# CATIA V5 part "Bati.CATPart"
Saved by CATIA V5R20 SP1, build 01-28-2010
Part number: Bati
Bounding box of the stored display mesh (mm): x -64.269 to 244.867, y -28.958 to 420.512, z -389.838 to 29.967
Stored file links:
  C:\Users\RENARD Simon\Documents\Cours IFMA\2ème année\IAO\Bati.CATPart
  C:\Users\RENARD Simon\Documents\Cours IFMA\2ème année\IAO\Trainattero.CATProduct
  C:\Users\RENARD Simon\Documents\Cours IFMA\2ème année\IAO\Sqbati.CATPart
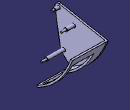
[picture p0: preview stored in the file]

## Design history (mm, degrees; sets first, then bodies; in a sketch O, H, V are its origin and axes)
Set1
  Plane1: linked copy from another document
  Line1 to Line3: linked copy from another document
Body1 (main body)
  Sketch1 on Plane1, origin (-63.6551, 1.3036, 0), H (0.0205, 0.9998, 0), V (0, 0, 1)
    point P1 (116.5347, -389.838)
    line L1 (116.5347, -389.838) -> (26.4996, -310.5054)
    arc A1 centre (46.3327, -287.9966) radius 30 from (26.4996, -310.5054) to (16.7136, -292.7617) cw
    point P3 (46.3327, -287.9966)
    line L2 (16.7136, -292.7617) -> (-29.6191, -4.7651)
    arc A2 centre (0, 0) radius 30 from (-29.6191, -4.7651) to (4.8723, 29.6017) cw
    point P6 (0, 0)
    line L3 (4.8723, 29.6017) -> (419.2961, -38.6108)
    point P8 (419.2961, -38.6108)
    reference projected point E1 (46.3327, -287.9966) from Line2
    reference projected point E2 (0, 0) from Line1
    spline S1 through (116.5347, -389.838) (177.4045, -353.8746) (419.2961, -38.6108)
    point P9 (116.5347, -389.838)
    point P10 (419.2961, -38.6108)
    radius A1 = 30
    radius A2 = 30
    length L1 = 120
    length L3 = 420
    tangency: A1 L1, A2 L2, L2 A1, L3 A2
    coincidence: P3 E1, P6 E2, P9 L1, P10 P8, P9 P1
  Pad1: profile Sketch1, direction (0.9998, -0.0205, 0), length 15
  Sketch2 on end face of Pad1, origin (-48.6582, 0.9965, 0), H (0.0205, 0.9998, 0), V (0, 0, 1)
    spline S1 through (116.5347, -389.838) (193.2598, -342.5189) (419.2961, -38.6108)
    reference projected point E1 (116.5347, -389.838) from vertex [face of Pad1 from Sketch1.L1 | end face of Pad1 | face of Pad1 from Sketch1.S1]
    reference projected point E2 (419.2961, -38.6108) from vertex [face of Pad1 from Sketch1.L3 | end face of Pad1 | face of Pad1 from Sketch1.S1]
    spline S2 through (105.2803, -379.9214) (214.7918, -307.121) (404.4952, -36.1746)
    reference projected line E3 (28.2255, -312.0261) -> (80.4295, -358.0246) from edge [face of Pad1 from Sketch1.L1 | end face of Pad1]
    reference projected line E4 (306.2958, -20.0114) -> (4.8723, 29.6017) from edge [face of Pad1 from Sketch1.L3 | end face of Pad1]
    line L1 (419.2961, -38.6108) -> (404.4952, -36.1746)
    point P1 (404.4952, -36.1746)
    point P2 (419.2961, -38.6108)
    line L2 (116.5347, -389.838) -> (105.2803, -379.9214)
    point P3 (105.2803, -379.9214)
    point P4 (116.5347, -389.838)
    reference projected curve E5 from edge [face of Pad1 from Sketch1.S1 | end face of Pad1]
    reference projected line E6 (306.2958, -20.0114) -> (4.8723, 29.6017) from edge [face of Pad1 from Sketch1.L3 | end face of Pad1]
    reference projected line E7 (28.2255, -312.0261) -> (80.4295, -358.0246) from edge [face of Pad1 from Sketch1.L1 | end face of Pad1]
    point P5 (116.5347, -389.838)
    point P6 (419.2961, -38.6108)
    point P7 (105.2803, -379.9214)
    point P8 (404.4952, -36.1746)
    length L2 = 15
    distance S2 S1 = 15
    length L1 = 15
    coincidence: E1 P5, P6 E2, P7 E3, P8 E4, L1 P8, P6 P2, P7 P3, P5 P4, P1 P8, L1 E6, L2 E7
    tangency: S1 E5
  Pad2: profile Sketch2, direction (0.9998, -0.0205, 0), length 285
  Point1: type OnSurface, Support face of Pad2 from Sketch2.S1, Length 23.586, Direction (-0.6669, -0.4871, -0.564)
  Plane2: type Tangent, Support face of Pad2 from Sketch2.S1, RefPoint Point1
  Sketch3 on Plane2, origin (5.841, 285.2088, -260.7679), H (0.9998, -0.0205, 0), V (0.0138, 0.6746, 0.7381)
    line L1 (31.3316, 189.2587) -> (211.3316, 189.2587)
    line L2 (211.3316, 189.2587) -> (211.3316, -177.8285)
    line L3 (211.3316, -177.8285) -> (31.3316, -177.8285)
    line L4 (31.3316, -177.8285) -> (31.3316, 189.2587)
    reference projected line E1 (236.3316, 246.2127) -> (236.3316, -209.3844) from edge [face of Pad2 from Sketch2.S2 | end face of Pad2]
    reference projected line E2 (-48.6684, 246.2127) -> (-48.6684, -209.3844) from edge [end face of Pad1 | face of Pad2 from Sketch2.S2]
    distance L2 E1 = 25
    distance L4 E2 = 80
    horizontal: L1 H, L3 H
    vertical: L2 V, L4 V
  Pocket1: profile Sketch3, direction (-0.0151, -0.7379, 0.6747), length 250
  Sketch4 on end face of Pad1, origin (-48.6582, 0.9965, 0), H (0.0205, 0.9998, 0), V (0, 0, 1)
    circle A1 centre (46.3327, -287.9966) radius 15
    point P1 (46.3327, -287.9966)
    reference projected point E1 (46.3327, -287.9966) from Line2
    radius A1 = 15
    coincidence: P1 E1
  Pad3: profile Sketch4, direction (0.9998, -0.0205, 0), length 145
  Sketch5 on end face of Pad1, origin (-48.6582, 0.9965, 0), H (0.0205, 0.9998, 0), V (0, 0, 1)
    circle A1 centre (0, 0) radius 15
    point P1 (0, 0)
    reference projected point E1 (0, 0) from Line1
    radius A1 = 15
    coincidence: P1 E1
  Pad4: profile Sketch5, direction (0.9998, -0.0205, 0), length 35
  Sketch6 on end face of Pad4, origin (-13.6656, 0.2799, 0), H (0.0205, 0.9998, 0), V (0, 0, 1)
    circle A1 centre (0, 0) radius 7.5
    point P1 (0, 0)
    reference projected point E1 (0, 0) from Line1
    radius A1 = 7.5
    coincidence: P1 E1
  Pad5: profile Sketch6, direction (0.9998, -0.0205, 0), length 20
  Sketch7 on end face of Pad3, origin (96.3114, -1.9724, 0), H (0.0205, 0.9998, 0), V (0, 0, 1)
    circle A1 centre (46.3327, -287.9966) radius 7.5
    point P1 (46.3327, -287.9966)
    reference projected point E1 (46.3327, -287.9966) from Line2
    radius A1 = 7.5
    coincidence: P1 E1
  Pad6: profile Sketch7, direction (0.9998, -0.0205, 0), length 40
  Sketch8 on end face of Pad1, origin (-48.6582, 0.9965, 0), H (0.0205, 0.9998, 0), V (0, 0, 1)
    circle A1 centre (132.5551, -65.0484) radius 15
    point P1 (132.5551, -65.0484)
    reference projected point E1 (132.5551, -65.0484) from Line3
    radius A1 = 15
    coincidence: P1 E1
  Pad7: profile Sketch8, direction (0.9998, -0.0205, 0), length 65
  Sketch9 on end face of Pad7, origin (16.3281, -0.3344, 0), H (0.0205, 0.9998, 0), V (0, 0, 1)
    circle A1 centre (132.5551, -65.0484) radius 7.5
    point P1 (132.5551, -65.0484)
    reference projected point E1 (132.5551, -65.0484) from Line3
    radius A1 = 7.5
    coincidence: P1 E1
  Pad8: profile Sketch9, direction (0.9998, -0.0205, 0), length 40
